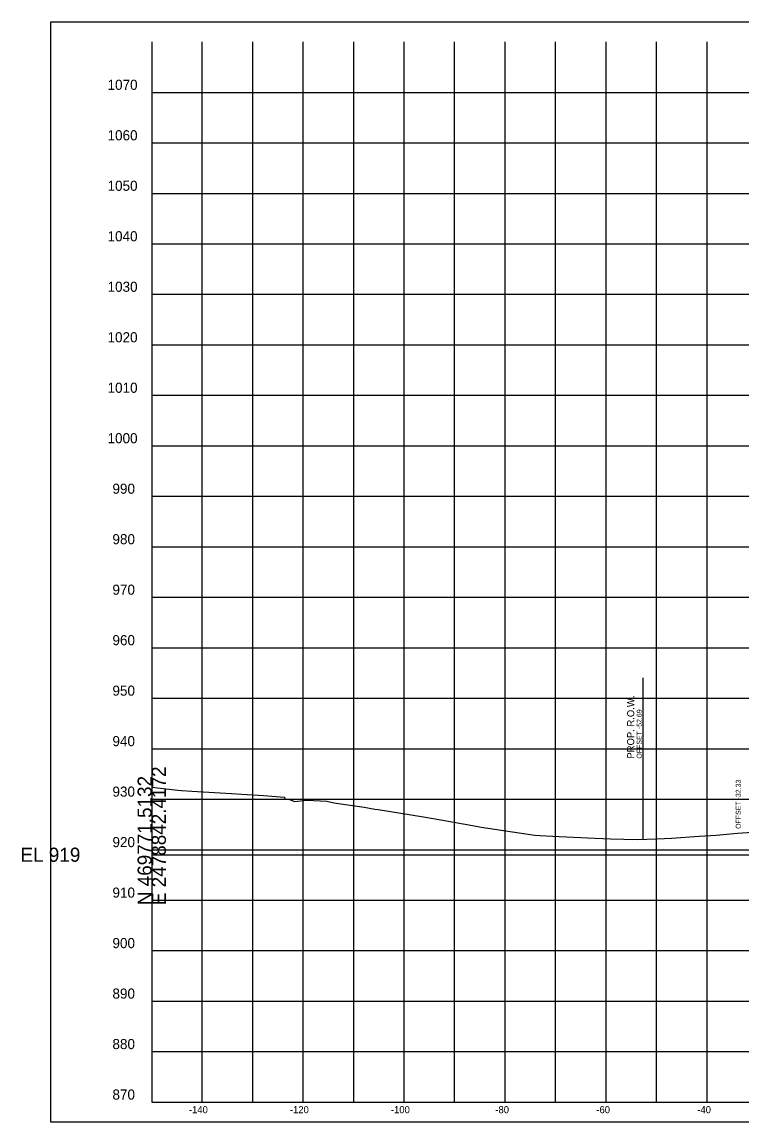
# Model space of a CAD drawing. Extents: x -26 to 2478923, y -10 to 469990.
# Drawn here: x -25.7 to 116.9, y 2947.1 to 3164.9 of the extents above; entities that cross this region are included whole.
import ezdxf

# ---------------------------------------------------------------- set-up
doc = ezdxf.new("R2010")
doc.units = 0
for name, color, linetype in [('DESIGN - ROW - Right-of-Way and Easement Labels', 7, 'Continuous'), ('DESIGN - ROW - Right-of-Way Linework', 7, 'Continuous'), ('DESIGN - SHEET - Corner Text', 7, 'Continuous'), ('DESIGN - SHEET - Light Grid', 7, 'Continuous'), ('DESIGN - SHEET - Linework', 7, 'Continuous'), ('DESIGN - SHEET - Plot Shape', 7, 'Continuous'), ('DESIGN - TYPICAL - Slope Tie Text', 7, 'Continuous'), ('SURVEY - GROUND - Top of Ground', 7, 'Continuous')]:
    doc.layers.add(name, color=color, linetype=linetype)

msp = doc.modelspace()

# ---------------------------------------------------------------- linework, layer by layer
at = {"layer": 'DESIGN - ROW - Right-of-Way Linework'}
msp.add_line((97.31, 3003.04), (97.31, 3035.04), dxfattribs=at)
at = {"layer": 'DESIGN - SHEET - Light Grid'}
msp.add_line((0, 3000), (150, 3000), dxfattribs=at)
at = {"layer": 'DESIGN - SHEET - Linework'}
for p, q in [((10, 2951), (10, 3161)), ((10, 2951), (10, 3161)), ((10, 2951), (10, 3161)), ((10, 2951), (10, 3161)), ((20, 2951), (20, 3161)), ((20, 2951), (20, 3161)), ((20, 2951), (20, 3161)), ((20, 2951), (20, 3161)), ((30, 2951), (30, 3161)), ((30, 2951), (30, 3161)), ((30, 2951), (30, 3161)), ((30, 2951), (30, 3161)), ((40, 2951), (40, 3161)), ((40, 2951), (40, 3161)), ((40, 2951), (40, 3161)), ((40, 2951), (40, 3161)), ((50, 2951), (50, 3161)), ((50, 2951), (50, 3161)), ((50, 2951), (50, 3161)), ((50, 2951), (50, 3161)), ((60, 2951), (60, 3161)), ((60, 2951), (60, 3161)), ((60, 2951), (60, 3161)), ((60, 2951), (60, 3161)), ((70, 2951), (70, 3161)), ((70, 2951), (70, 3161)), ((70, 2951), (70, 3161)), ((70, 2951), (70, 3161)), ((80, 2951), (80, 3161)), ((80, 2951), (80, 3161)), ((80, 2951), (80, 3161)), ((80, 2951), (80, 3161)), ((90, 2951), (90, 3161)), ((90, 2951), (90, 3161)), ((90, 2951), (90, 3161)), ((90, 2951), (90, 3161)), ((100, 2951), (100, 3161)), ((100, 2951), (100, 3161)), ((100, 2951), (100, 3161)), ((100, 2951), (100, 3161)), ((110, 2951), (110, 3161)), ((110, 2951), (110, 3161)), ((110, 2951), (110, 3161)), ((110, 2951), (110, 3161)), ((0, 3151), (300, 3151)), ((0, 3151), (300, 3151)), ((0, 3151), (300, 3151)), ((0, 3151), (300, 3151)), ((0, 3141), (300, 3141)), ((0, 3141), (300, 3141)), ((0, 3141), (300, 3141)), ((0, 3141), (300, 3141)), ((0, 3131), (300, 3131)), ((0, 3131), (300, 3131)), ((0, 3131), (300, 3131)), ((0, 3131), (300, 3131)), ((0, 3121), (300, 3121)), ((0, 3121), (300, 3121)), ((0, 3121), (300, 3121)), ((0, 3121), (300, 3121)), ((0, 3111), (300, 3111)), ((0, 3111), (300, 3111)), ((0, 3111), (300, 3111)), ((0, 3111), (300, 3111)), ((0, 3101), (300, 3101)), ((0, 3101), (300, 3101)), ((0, 3101), (300, 3101)), ((0, 3101), (300, 3101)), ((0, 3091), (300, 3091)), ((0, 3091), (300, 3091)), ((0, 3091), (300, 3091)), ((0, 3091), (300, 3091)), ((0, 3081), (300, 3081)), ((0, 3081), (300, 3081)), ((0, 3081), (300, 3081)), ((0, 3081), (300, 3081)), ((0, 3071), (300, 3071)), ((0, 3071), (300, 3071)), ((0, 3071), (300, 3071)), ((0, 3071), (300, 3071)), ((0, 3061), (300, 3061)), ((0, 3061), (300, 3061)), ((0, 3061), (300, 3061)), ((0, 3061), (300, 3061)), ((0, 3051), (300, 3051)), ((0, 3051), (300, 3051)), ((0, 3051), (300, 3051)), ((0, 3051), (300, 3051)), ((0, 3041), (300, 3041)), ((0, 3041), (300, 3041)), ((0, 3041), (300, 3041)), ((0, 3041), (300, 3041)), ((0, 3031), (300, 3031)), ((0, 3031), (300, 3031)), ((0, 3031), (300, 3031)), ((0, 3031), (300, 3031)), ((0, 3021), (300, 3021)), ((0, 3021), (300, 3021)), ((0, 3021), (300, 3021)), ((0, 3021), (300, 3021)), ((0, 3011), (300, 3011)), ((0, 3011), (300, 3011)), ((0, 3011), (300, 3011)), ((0, 3011), (300, 3011)), ((0, 3001), (300, 3001)), ((0, 3001), (300, 3001)), ((0, 3001), (300, 3001)), ((0, 3001), (300, 3001)), ((0, 2991), (300, 2991)), ((0, 2991), (300, 2991)), ((0, 2991), (300, 2991)), ((0, 2991), (300, 2991)), ((0, 2981), (300, 2981)), ((0, 2981), (300, 2981)), ((0, 2981), (300, 2981)), ((0, 2981), (300, 2981)), ((0, 2971), (300, 2971)), ((0, 2971), (300, 2971)), ((0, 2971), (300, 2971)), ((0, 2971), (300, 2971)), ((0, 2961), (300, 2961)), ((0, 2961), (300, 2961)), ((0, 2961), (300, 2961)), ((0, 2961), (300, 2961))]:
    msp.add_line(p, q, dxfattribs=at)
msp.add_lwpolyline([(0, 3161), (0, 2951), (300, 2951), (300, 3161)], dxfattribs=at)
msp.add_lwpolyline([(0, 3161), (0, 2951), (300, 2951), (300, 3161)], dxfattribs=at)
msp.add_lwpolyline([(0, 3161), (0, 2951), (300, 2951), (300, 3161)], dxfattribs=at)
msp.add_lwpolyline([(0, 3161), (0, 2951), (300, 2951), (300, 3161)], dxfattribs=at)
at = {"layer": 'DESIGN - SHEET - Plot Shape'}
msp.add_lwpolyline([(-20, 3164.94), (320, 3164.94), (320, 2947.06), (-20, 2947.06)], close=True, dxfattribs=at)
msp.add_lwpolyline([(-20, 3164.94), (320, 3164.94), (320, 2947.06), (-20, 2947.06)], close=True, dxfattribs=at)
msp.add_lwpolyline([(-20, 3164.94), (320, 3164.94), (320, 2947.06), (-20, 2947.06)], close=True, dxfattribs=at)
msp.add_lwpolyline([(-20, 3164.94), (320, 3164.94), (320, 2947.06), (-20, 2947.06)], close=True, dxfattribs=at)
at = {"layer": 'SURVEY - GROUND - Top of Ground'}
msp.add_lwpolyline([(0, 3013.37), (5.18, 3012.79), (5.89, 3012.75), (7.92, 3012.61), (15.83, 3012.14), (17.88, 3012.02), (22.15, 3011.7), (26.27, 3011.42), (26.39, 3011.1), (27.13, 3010.98), (28.25, 3010.57), (30.72, 3010.8), (34.68, 3010.58), (36.15, 3010.27), (36.55, 3010.18), (42.07, 3009.4), (44.22, 3009.05), (44.84, 3008.95), (53.81, 3007.52), (57.25, 3006.88), (64.27, 3005.64), (65.25, 3005.48), (75.85, 3003.87), (76.89, 3003.81), (80.7, 3003.58), (85.01, 3003.39), (86.29, 3003.32), (90.84, 3003.15), (96.17, 3003), (100.04, 3003.13), (102.97, 3003.25), (108.41, 3003.7), (111.77, 3003.89), (116.04, 3004.26), (124.95, 3004.86)], dxfattribs=at)

# ---------------------------------------------------------------- texts
at = {"layer": 'DESIGN - ROW - Right-of-Way and Easement Labels'}
for s, height, p in [('PROP. R.O.W.', 1.4, (95.56, 3019.04)), ('OFFSET -52.69', 1, (97.06, 3019.04))]:
    msp.add_text(s, height=height, rotation=90, dxfattribs=at).set_placement(p)
at = {"layer": 'DESIGN - SHEET - Corner Text'}
for s, height, p in [('1070', 2, (-8.75, 3151.5)), ('1070', 2, (-8.75, 3151.5)), ('1070', 2, (-8.75, 3151.5)), ('1070', 2, (-8.75, 3151.5)), ('1060', 2, (-8.75, 3141.5)), ('1060', 2, (-8.75, 3141.5)), ('1060', 2, (-8.75, 3141.5)), ('1060', 2, (-8.75, 3141.5)), ('1050', 2, (-8.75, 3131.5)), ('1050', 2, (-8.75, 3131.5)), ('1050', 2, (-8.75, 3131.5)), ('1050', 2, (-8.75, 3131.5)), ('1040', 2, (-8.75, 3121.5)), ('1040', 2, (-8.75, 3121.5)), ('1040', 2, (-8.75, 3121.5)), ('1040', 2, (-8.75, 3121.5)), ('1030', 2, (-8.75, 3111.5)), ('1030', 2, (-8.75, 3111.5)), ('1030', 2, (-8.75, 3111.5)), ('1030', 2, (-8.75, 3111.5)), ('1020', 2, (-8.75, 3101.5)), ('1020', 2, (-8.75, 3101.5)), ('1020', 2, (-8.75, 3101.5)), ('1020', 2, (-8.75, 3101.5)), ('1010', 2, (-8.75, 3091.5)), ('1010', 2, (-8.75, 3091.5)), ('1010', 2, (-8.75, 3091.5)), ('1010', 2, (-8.75, 3091.5)), ('1000', 2, (-8.75, 3081.5)), ('1000', 2, (-8.75, 3081.5)), ('1000', 2, (-8.75, 3081.5)), ('1000', 2, (-8.75, 3081.5)), ('990', 2, (-7.78, 3071.5)), ('990', 2, (-7.78, 3071.5)), ('990', 2, (-7.78, 3071.5)), ('990', 2, (-7.78, 3071.5)), ('980', 2, (-7.78, 3061.5)), ('980', 2, (-7.78, 3061.5)), ('980', 2, (-7.78, 3061.5)), ('980', 2, (-7.78, 3061.5)), ('970', 2, (-7.78, 3051.5)), ('970', 2, (-7.78, 3051.5)), ('970', 2, (-7.78, 3051.5)), ('970', 2, (-7.78, 3051.5)), ('960', 2, (-7.78, 3041.5)), ('960', 2, (-7.78, 3041.5)), ('960', 2, (-7.78, 3041.5)), ('960', 2, (-7.78, 3041.5)), ('950', 2, (-7.78, 3031.5)), ('950', 2, (-7.78, 3031.5)), ('950', 2, (-7.78, 3031.5)), ('950', 2, (-7.78, 3031.5)), ('940', 2, (-7.78, 3021.5)), ('940', 2, (-7.78, 3021.5)), ('940', 2, (-7.78, 3021.5)), ('940', 2, (-7.78, 3021.5)), ('930', 2, (-7.78, 3011.5)), ('930', 2, (-7.78, 3011.5)), ('930', 2, (-7.78, 3011.5)), ('930', 2, (-7.78, 3011.5)), ('920', 2, (-7.78, 3001.5)), ('920', 2, (-7.78, 3001.5)), ('920', 2, (-7.78, 3001.5)), ('920', 2, (-7.78, 3001.5)), ('910', 2, (-7.78, 2991.5)), ('910', 2, (-7.78, 2991.5)), ('910', 2, (-7.78, 2991.5)), ('910', 2, (-7.78, 2991.5)), ('900', 2, (-7.78, 2981.5)), ('900', 2, (-7.78, 2981.5)), ('900', 2, (-7.78, 2981.5)), ('900', 2, (-7.78, 2981.5)), ('890', 2, (-7.78, 2971.5)), ('890', 2, (-7.78, 2971.5)), ('890', 2, (-7.78, 2971.5)), ('890', 2, (-7.78, 2971.5)), ('880', 2, (-7.78, 2961.5)), ('880', 2, (-7.78, 2961.5)), ('880', 2, (-7.78, 2961.5)), ('880', 2, (-7.78, 2961.5)), ('870', 2, (-7.78, 2951.5)), ('870', 2, (-7.78, 2951.5)), ('870', 2, (-7.78, 2951.5)), ('870', 2, (-7.78, 2951.5)), ('-140', 1.4, (7.37, 2948.8)), ('-140', 1.4, (7.37, 2948.8)), ('-140', 1.4, (7.37, 2948.8)), ('-140', 1.4, (7.37, 2948.8)), ('-120', 1.4, (27.37, 2948.8)), ('-120', 1.4, (27.37, 2948.8)), ('-120', 1.4, (27.37, 2948.8)), ('-120', 1.4, (27.37, 2948.8)), ('-100', 1.4, (47.37, 2948.8)), ('-100', 1.4, (47.37, 2948.8)), ('-100', 1.4, (47.37, 2948.8)), ('-100', 1.4, (47.37, 2948.8)), ('-80', 1.4, (68.06, 2948.8)), ('-80', 1.4, (68.06, 2948.8)), ('-80', 1.4, (68.06, 2948.8)), ('-80', 1.4, (68.06, 2948.8)), ('-60', 1.4, (88.06, 2948.8)), ('-60', 1.4, (88.06, 2948.8)), ('-60', 1.4, (88.06, 2948.8)), ('-60', 1.4, (88.06, 2948.8)), ('-40', 1.4, (108.06, 2948.8)), ('-40', 1.4, (108.06, 2948.8)), ('-40', 1.4, (108.06, 2948.8)), ('-40', 1.4, (108.06, 2948.8))]:
    msp.add_text(s, height=height, dxfattribs=at).set_placement(p)
at = {"layer": 'DESIGN - SHEET - Light Grid'}
for s, p in [('E 2478842.4172', (2.8, 2990)), ('N 469771.5132', (0, 2990))]:
    msp.add_text(s, height=2.8, rotation=90, dxfattribs=at).set_placement(p)
msp.add_text('EL 919', height=2.8, dxfattribs=at).set_placement((-26, 2998.6))
at = {"layer": 'DESIGN - TYPICAL - Slope Tie Text'}
msp.add_text('OFFSET -32.33', height=1, rotation=90, dxfattribs=at).set_placement((116.67, 3005.12))

doc.saveas('drawing.dxf')
